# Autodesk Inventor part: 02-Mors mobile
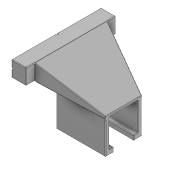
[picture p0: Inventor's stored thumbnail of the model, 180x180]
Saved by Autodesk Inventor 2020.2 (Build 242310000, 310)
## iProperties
Created: 2022-02
Part Number: 02-Mors mobile
Material: Fonte, moulé
Document SubType Name: Modeling
Designer: Philippe
Density: 7.15 g/cm^3
Appearance: Gris clair
Author: Philippe
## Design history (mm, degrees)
derived "Base-Etau.ipt"
sketch "Esquisse1"
  geometry: C1 r 5.053 at (12, 7) reference; A1 r 6 centre (12, 7) between (6, 7) and (12, 13); 1 further point
  constraints: 2 point on circle, 1 centre point, 1 coincident, 1 horizontal alignment, 1 vertical alignment
  dimensions: "d1" = 6 radius of A1
feature "SrfExtrusion1" sketch "Esquisse1" dims "d2" = 0.5, "d3" = 10.5, "d4" = 0, "d5" = 0
feature "02-Mors mobile::Base-Etau.ipt" dims "d0" = 10
tag "FonctionRepérage1"
body "Srf1"
node "Solide1"
